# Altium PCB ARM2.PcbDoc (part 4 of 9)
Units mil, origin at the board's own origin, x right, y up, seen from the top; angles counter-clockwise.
Board outline 4700.79 x 3937.01 mil, 6 copper layers (Top Layer, GND02, ART03, ART04, PWR05, Bottom Layer); 697 components, 508 nets, 2326 pads, 1231 vias.
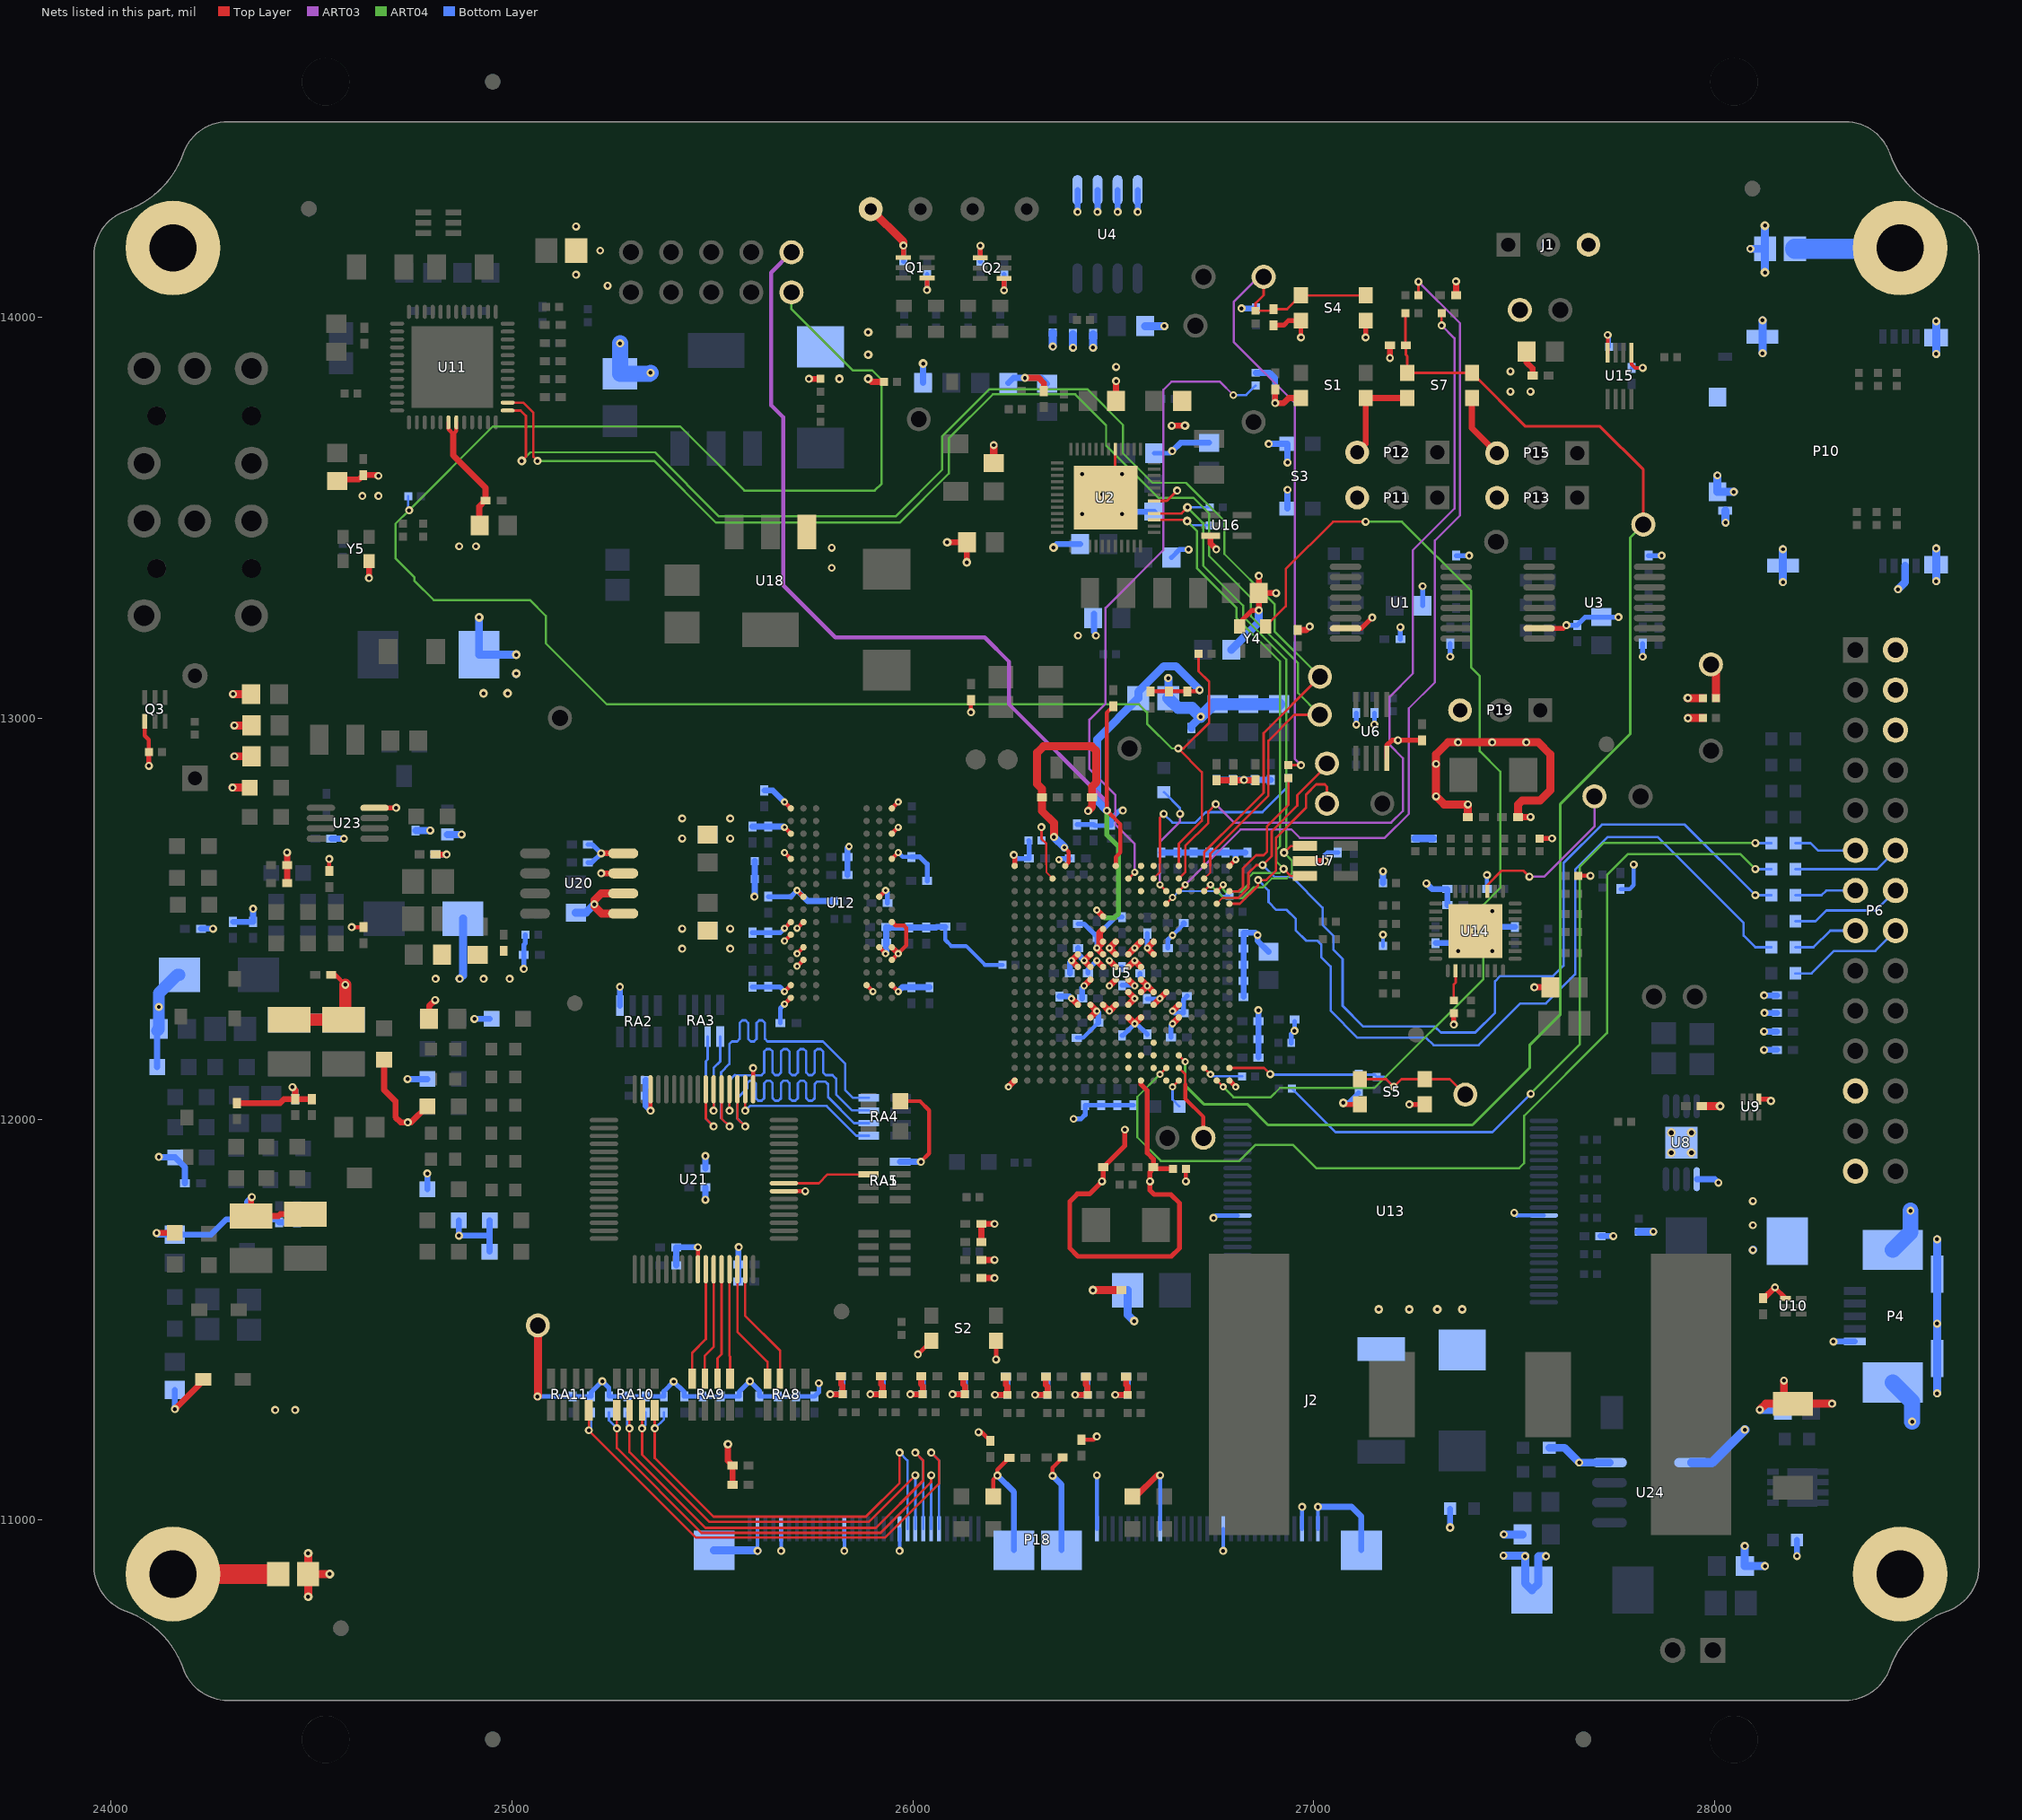
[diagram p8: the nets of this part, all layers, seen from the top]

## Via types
v1: diameter 20, hole 10, Top Layer to Bottom Layer, tented both sides, 871 vias
v2: diameter 18, hole 8, Top Layer to Bottom Layer, tented both sides, 273 vias
v3: diameter 22, hole 10, Top Layer to Bottom Layer, tented both sides, 64 vias
v4: diameter 20, hole 10, Top Layer to Bottom Layer, 18 vias
v5: diameter 22, hole 12, Top Layer to Bottom Layer, 4 vias
v6: diameter 39.37, hole 19.68, Top Layer to Bottom Layer, 1 vias

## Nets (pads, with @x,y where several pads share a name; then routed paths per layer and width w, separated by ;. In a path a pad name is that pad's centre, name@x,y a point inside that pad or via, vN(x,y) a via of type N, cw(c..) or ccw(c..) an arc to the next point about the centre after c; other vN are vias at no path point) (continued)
DGND: C1.1 C2.1 C3.1 C4.1 C5.2 C6.2 C7.1 C8.1 C9.1 C10.1 C11.1 C12.1 C13.1 C14.1 C15.1 C16.2 C17.2 C18.2 C19.2 C20.2 C23.2 C24.2 C27.2 C28.2 C29.2 C30.2 C34.2 C35.2 C36.2 C37.2 C38.2 C39.1 C40.1 C41.2 C42.2 C43.2 C44.2 C45.2 C46.2 C47.2 C48.2 C49.2 C50.2 C51.2 C52.2 C53.2 C54.2 C55.1 C56.1 C57.1 C58.2 C59.2 C60.1 C61.1 C62.1 C63.2 C64.2 C65.2 C66.2 C67.2 C68.1 C69.1 C70.1 C71.1 C72.1 C73.1 C74.1 C75.1 C76.1 C77.2 C78.2 C79.2 C80.2 C81.2 C82.2 C83.2 C84.2 C85.2 C86.2 C87.2 C88.2 C89.2 C90.2 C91.2 C92.2 C94.2 C95.1 C96.1 C97.2 C98.2 C99.2 C100.2 C101.2 C102.2 C103.2 C104.2 C105.2 C106.2 C107.2 C108.2 C109.2 C110.2 C111.2 C112.2 C113.2 C114.2 C115.2 C116.2 C117.2 C118.1 C119.2 C120.2 C121.2 C122.1 C123.2 C124.2 C125.2 C126.1 C127.2 C128.2 C129.2 C131.2 C132.2 C133.1 C134.2 C135.2 C136.2 C137.2 C138.2 C139.2 C140.2 C141.2 C142.2 C143.2 C145.2 C146.2 C147.2 C148.2 C149.2 C150.1 C151.2 C152.2 C153.2 C154.2 C155.1 C156.2 C157.2 C158.2 C159.2 C160.2 C161.2 C162.2 C163.2 C164.2 C165.2 C166.2 C167.2 C168.2 C169.2 C170.2 C171.2 C172.2 C173.2 C174.2 C189.2 C190.1 C191.2 C192.1 C197.2 C198.2 C199.2 C200.2 C201.2 C202.2 C204.1 C205.1 C206.1 C207.2 C208.2 C209.2 C210.2 C211.2 C212.2 C213.2 C214.2 C215.2 C216.2 C217.2 C218.2 C219.2 C220.2 C221.2 C222.2 C223.2 C224.2 C225.2 C226.2 C227.2 C228.2 C229.2 C230.2 C231.2 C232.2 C233.2 C234.2 C235.2 C236.2 C237.2 C238.2 C239.2 C240.2 C242.1 C243.1 C244.1 C245.1 C246.1 C249.1 C250.2 C251.1 C252.1 C253.1 C254.1 C256.2 C257.2 C258.1 C260.1 C261.1 C262.2 C263.2 C264.2 C265.2 C266.2 C267.2 C268.2 C269.2 C270.2 C271.2 C272.2 C273.2 C274.2 C275.2 C276.2 C277.2 C281.2 C282.2 D10.2 FB3.2 FB9.2 FB10.1 FB11.1 J1.3 J2.1 P4.5 P6.2 P6.4 P6.6 P6.23 P6.27 P10.6 P10.9 P11.3 P12.3 P13.3 P15.3 P18.2 P18.5 P18.13 P18.20 P18.31 P18.32 P18.33 P18.41 P18.49 P18.59 P18.61 P18.63 P18.64 P19.3 Q1.1 Q1.4 Q2.1 Q2.4 Q3.1 R10.2 R12.1 R22.1 R25.2 R34.2 R36.2 R39.1 R49.1 R53.2 R54.1 R76.2 R77.2 R78.2 R79.2 R80.2 R81.2 R82.2 R83.2 R84.2 R85.2 R86.2 R87.2 R88.2 R89.2 R90.2 R91.2 R92.2 R93.2 R94.2 R95.2 R96.1 R99.1 R100.2 R110.2 R115.2 R116.2 R117.2 R118.2 R130.1 R132.1 R135.2 R144.2 R145.2 R149.2 R164.2 R165.2 R169.2 R170.2 R173.1 R175.2 R176.1 R178.2 R190.2 R191.2 R198.2 R199.2 R201.1 R207.2 R208.2 R209.2 R210.2 R214.1 R215.1 R217.1 R238.2 RA2.1 RA5.1 S1.1 S1.3 S2.2 S2.4 S3.1 S3.3 S4.1 S4.3 S5.1 S5.3 S7.1 S7.3 TP1.1 TP8.1 TP9.1 U1.15 U2.30 U2.41 U2.49 U3.15 U4.5 U4.6 U4.7 U4.8 U5.A1 U5.A18 U5.F8 U5.G8 U5.G9 U5.G11 U5.G12 U5.H6 U5.H7 U5.H8 U5.H9 U5.H10 U5.H12 U5.J6 U5.J7 U5.J8 U5.J9 U5.J10 U5.J11 U5.K7 U5.K9 U5.K10 U5.K11 U5.L10 U5.L11 U5.L12 U5.L13 U5.M6 U5.M7 U5.M8 U5.M9 U5.M10 U5.M12 U5.M14 U5.N7 U5.N10 U5.N11 U5.N14 U5.V1 U5.V18 U6.4 U7.2 U8.1 U8.9 U9.4 U10.4 U11.42 U11.43 U12.A9 U12.B1 U12.B3 U12.B9 U12.D1 U12.D8 U12.E1 U12.E2 U12.E8 U12.F9 U12.G1 U12.G8 U12.G9 U12.J2 U12.J8 U12.M1 U12.M9 U12.P1 U12.P9 U12.T1 U12.T9 U13.13 U13.36 U14.33 U15.1 U15.4 U16.3 U18.1 U20.5 U20.6 U20.7 U20.8 U21.25 U21.39 U21.49 U21.62 U23.4 U24.4 U24.5 Y4.2 Y5.2 | length 23904.7
  Top Layer w7: v4(26472.19,13558.86) 26504.67,13591.34 U2.41@26504.67,13671.06 ; U2.30@26602.12,13542.13 26633.68,13542.13 v1(26659.45,13567.9)
  Top Layer w9: U15.4@27733.1,13911.57 v1(27733.12,13955.69) ; U15.1@27792.12,13911.57 27792.12,13882.76 27801.31,13873.57 v1(27820.31,13873.57)
  Top Layer w10: Q3.1@24084.6,12992.54 24084.6,12956.66 24095.05,12946.21 R34.2@24095.05,12915.07 ; C265.2@24545,12619 v1(24545,12648.91) ; C266.2@24550,12360 24560,12360 v1(24585,12335) ; v1(24601,12479) C264.2@24630,12479 ; U11.42@24842.16,13737.82 24842.16,13720.46 24854,13708.62 24861.84,13716.46 U11.43@24861.84,13737.82 ; v1(25346.1,12021.21) U21.62@25346.1,12074.41 ; U21.25@25464.21,11625.59 v1(25464.21,11680.79) ; U21.49@25602.01,12074.41 v1(25602.01,12127.61) ; U21.39@25678.78,11820.47 v1(25731.98,11820.48) ; v2(25680.27,12287.01) U12.A9@25696.02,12302.75 ; v2(25680.27,12318.51) U12.B9@25696.02,12334.25 ; v2(25680.27,12444.49) U12.F9@25696.02,12460.23 ; v2(25680.27,12475.99) U12.G9@25696.02,12491.73 ; v2(25680.27,12664.96) U12.M9@25696.02,12649.21 ; v2(25680.27,12727.95) U12.P9@25696.02,12712.2 ; v2(25680.27,12790.94) U12.T9@25696.02,12775.19 ; v2(25711.77,12381.5) U12.D8@25727.51,12397.24 ; v2(25711.77,12412.99) U12.E8@25727.51,12428.73 ; v2(25711.77,12475.99) U12.G8@25727.51,12491.73 ; v2(25711.77,12570.47) U12.J8@25727.51,12554.72 ; U12.B3@25884.99,12334.25 v2(25900.73,12318.51) ; U12.E2@25916.49,12428.73 v2(25932.23,12412.99) ; U12.J2@25916.49,12554.72 v2(25932.23,12570.47) ; U12.B1@25947.98,12334.25 v2(25963.73,12318.51) ; U12.D1@25947.98,12397.24 v2(25963.73,12412.99) ; U12.G1@25947.98,12491.73 25956.71,12483 25978,12483 25984,12477 25984,12433.27 v2(25963.73,12412.99) ; U12.M1@25947.98,12649.21 v2(25963.73,12664.96) ; U12.P1@25947.98,12712.2 v2(25963.73,12727.95) ; U12.T1@25947.98,12775.19 v2(25963.73,12790.94) ; R191.2@25968.74,12045 26018,12045 26041,12022 26041,11914.49 v1(26020.26,11893.74) ; v1(26145,13015) C106.2@26145,13045 ; v1(26164,11219.62) 26171.61,11219.62 C207.2@26193.28,11197.95 ; R169.2@26200.39,11059.16 26200.39,11101.01 v1(26211,11111.62) 26211,11125.62 C231.2@26241,11155.62 ; v1(26349,11110.62) 26349,11131.62 C211.2@26374,11156.62 ; C232.2@26421,11200.62 26451,11200.62 v1(26459,11208.62) ; v1@26681.27,11844.75 R110.2@26681.27,11875.57 ; U5.A18@26789.7,12631.72 v2(26805.45,12647.47) ; R144.2@27660,12607 v1(27690,12607)
  Top Layer w11: v1(26012.79,11413.62) S2.4@26046.29,11447.12 ; v1(26207.71,11400.91) S2.2@26207.71,11447.12
  Top Layer w12: v1(24095.05,12881.21) R34.2@24095.05,12915.07 ; U23.4@24657.93,12776.39 v1(24711.8,12776.39) ; Q1.4@25976.67,14148.81 v1(25976.67,14178.69) ; v1(26035.72,14067.75) Q1.1@26035.72,14097.63 ; Q2.4@26168.67,14148.18 v1(26168.67,14178.06) ; v1(26227.72,14067.12) Q2.1@26227.72,14097 ; v1(26252,12659.28) 26254.26,12657.02 U5.A1@26254.26,12631.72 ; U5.V18@26789.7,12096.28 v2(26805.45,12080.54) ; Y4.2@26815,13229 26815,13238.45 26845.55,13269 v1(26863,13269) ; C145.2@26900,13980 26925.46,13980 26936.96,13991.5 S4.1@26968.02,13991.5 v1(26968.02,13949.57) ; v3(27073.5,12040.88) 27077.5,12036.88 S5.1@27115.29,12036.88 ; U1.15@27079.41,13224.01 27118.92,13224.01 v1(27145.86,13250.94) ; v1(27129.44,13949.57) S4.3@27129.44,13991.5 ; U6.4@27182,12900 27182,12932 27195,12945 v1(27209.96,12945) C27.2@27270,12945 ; v1(27238.5,12036.88) S5.3@27276.71,12036.88 ; v1(27349.22,12236.06) R145.2@27349.22,12263.92 ; U3.15@27562.07,13224.01 27622.01,13224.01 v1(27630,13232) ; R135.2@27563.11,12700.14 v1(27594.55,12700.14) ; U9.4@28109.81,12050.26 28135.44,12050.26 v3(28140.12,12045.57) ; v1@28149.58,11580.03 U10.4@28176.31,11553.3
  Top Layer w15: v1(24114.37,11716.37) R217.1@24160,11716.37 ; v1(24160,11277) 24230.79,11347.79 D10.2@24230.79,11351.5 ; C276.2@24315,12040 24422,12040 24432,12050 C274.2@24460,12050 ; v1(24352,11806) 24350,11804 C246.1@24350,11758.31 24418,11758.31 24423,11763.31 C245.1@24485,11763.31 ; C267.2@24440,12589 C269.2@24440,12634 v1(24440,12665) ; v1(24453,12080) 24460,12073 C274.2@24460,12050 ; C258.1@24502,12050 C274.2@24460,12050 ; C192.1@24564.73,13591.35 24568.73,13595.35 24618.73,13595.35 C191.2@24629.73,13606.35 24665.47,13606.35 v1(24667.47,13604.35) ; v1(24644,13349.7) Y5.2@24644,13391.48 v1@24644,13350.7 ; R214.1@24681.81,12148.23 24681.81,12073.19 24710,12045 24710,12005 24723,11992 v1(24741,11992) 24749.13,11992 R198.2@24789.63,12032.5 ; C250.2@24794,12250 24794,12282 v1(24809,12297) ; C212.2@24805,12660 C212.2@24810,12660 v1(24837.37,12660) ; 24854,13708.62 24854,13655.62 24934.79,13574.83 24934.79,13544.63 24933.89,13543.73 24933.89,13542.83 24919.12,13528.06 C190.1@24919.12,13491.57 ; v1(25223,12613) U20.7@25278,12613 ; v1(25223,12663) U20.8@25278,12663 ; v3(25539.12,11189.57) 25539.12,11148.33 C216.2@25550.72,11136.73 C219.2@25550.72,11087.73 ; v1(25741.27,13846.27) R36.2@25770,13846.27 ; v1(25794.19,11313.94) R95.2@25825.05,11313.94 25825.05,11335.08 25821.19,11338.94 C173.2@25821.19,11358.94 ; v3(25889.12,13846.57) 25897.08,13838.62 R12.1@25928.86,13838.62 ; v1(25894.19,11313.94) R93.2@25925.05,11313.94 25925.05,11335.08 25921.19,11338.94 C172.2@25921.19,11358.94 ; U12.E1@25947.98,12428.73 v2(25963.73,12412.99) ; v1(25994.19,11313.94) R91.2@26025.05,11313.94 26025.05,11335.08 26021.19,11338.94 C169.2@26021.19,11358.94 ; v3(26086.08,13438.62) C1.1@26135,13438.62 v3(26135,13388.7) ; v1(26099.19,11313.94) R89.2@26130.05,11313.94 26130.05,11335.08 26126.19,11338.94 C162.2@26126.19,11358.94 ; C223.2@26171,11604 v1(26204,11604) ; C222.2@26171,11649 v1(26204,11649) ; C221.2@26171,11694 C220.2@26171,11739 v1(26204,11739) ; v1(26205.09,11312.56) R87.2@26235.94,11312.56 26235.94,11333.7 26232.09,11337.56 C160.2@26232.09,11357.56 ; v2(26238.51,12080.54) U5.V1@26254.26,12096.28 ; v1(26279.72,13848.72) 26314.28,13848.72 26327,13836 C3.1@26327,13816 ; v1(26305.09,11312.56) R83.2@26335.94,11312.56 26335.94,11333.7 26332.09,11337.56 C167.2@26332.09,11357.56 ; v1(26405.09,11312.56) R82.2@26435.94,11312.56 26435.94,11333.7 26432.09,11337.56 C166.2@26432.09,11357.56 ; v1(26505.09,11312.56) R81.2@26535.94,11312.56 26535.94,11333.7 26532.09,11337.56 C165.2@26532.09,11357.56 ; C15.1@26507,13791 v1(26507,13841) ; R170.2@26548.08,11059.16 26556.34,11059.16 26609.22,11112.04 v1(26616.77,11112.04) ; v2(26584.97,12426.99) U5.H12@26600.72,12411.24 ; v1(26646.12,13729.57) v3(26679.12,13729.57) ; U16.3@26742.63,13455.41 26742.63,13435.37 v1(26757,13421) ; C53.2@26758.02,12845 C48.2@26800,12845 v1@26825,12845 ; v1(26826,12846) v1@26825,12845 ; C54.2@26855,12845 v1@26825,12845 ; v1(26863,13269) C12.1@26863,13312 ; v1(26863,13355) C12.1@26863,13312 ; C24.2@26903.73,13820 v1(26903.73,13785.86) 26925,13785.86 26937.64,13798.5 S1.1@26968.02,13798.5 ; v1(26906,13312) C12.1@26863,13312 ; C159.2@26960,13220 26981.55,13220 v1(26990.12,13228.57) ; U7.2@26978,12644 v1(27028,12644) ; P12.3@27108.26,13663 27129.44,13684.18 S1.3@27129.44,13798.5 S7.1@27233.02,13798.5 ; C148.2@27190,13930 27190,13898.7 v1(27190.12,13898.57) ; C30.2@27355,14055 v1(27355,14089.45) ; S7.3@27394.44,13798.5 27394.44,13723.56 P15.3@27457,13661 ; C142.2@27509.3,12753.4 v1(27540.74,12753.4) ; C153.2@27531,13914.15 27531,13887.15 27546,13872.15 C154.2@27546,13854.15 ; v1(27550,12329) C133.1@27590,12329 ; C36.2@28123.17,11553.62 v1@28149.58,11580.03 ; R176.1@28172.62,11312.99 R176.1@28195.13,11290.49
  Top Layer w16: v2(26395.99,12301.01) U5.M6@26411.74,12285.26 ; U5.J6@26411.74,12379.75 v2(26395.99,12395.5) U5.H6@26411.74,12411.24 ; v2(26427.49,12332.51) U5.K7@26443.24,12348.25 ; U5.N7@26443.24,12253.76 v2(26458.99,12269.52) U5.M7@26443.24,12285.26 ; U5.J7@26443.24,12379.75 v2(26427.49,12395.5) U5.H7@26443.24,12411.24 ; v2(26458.99,12395.5) U5.J8@26474.74,12379.75 ; U5.M8@26474.74,12285.26 v2(26490.48,12269.52) U5.M9@26506.23,12285.26 ; U5.H8@26474.74,12411.24 v2(26458.99,12426.99) U5.G8@26469.18,12437.19 ; U5.G8@26474.74,12442.74 U5.G8@26469.18,12437.19 ; U5.F8@26474.74,12474.24 26466.1,12465.6 26466.1,12448.59 ; v2(26490.48,12332.51) U5.K9@26506.23,12348.25 ; v2(26490.48,12395.5) U5.J9@26506.23,12379.75 ; U5.H9@26506.23,12411.24 v2(26490.48,12426.99) U5.G9@26506.23,12442.74 ; U5.N10@26537.73,12253.76 v2(26553.48,12238.02) U5.N11@26569.22,12253.76 ; U5.M10@26537.73,12285.26 v2(26553.48,12301.02) U5.L10@26537.73,12316.76 ; U5.K10@26537.73,12348.25 v2(26553.48,12332.51) ; U5.J10@26537.73,12379.75 v2(26553.48,12395.5) U5.J11@26569.22,12379.75 ; U5.H10@26537.73,12411.24 v2(26553.48,12426.99) ; v2(26553.48,12426.99) U5.G11@26569.22,12442.74 ; U5.L11@26569.22,12316.76 v2(26584.97,12332.51) ; U5.K11@26569.22,12348.25 v2(26584.97,12332.51) ; v2(26584.97,12426.99) U5.G12@26600.72,12442.74 ; U5.M12@26600.72,12285.26 v2(26616.47,12301.02) U5.L13@26632.22,12316.76 ; U5.L12@26600.72,12316.76 v2(26584.97,12332.51) ; v2(26647.96,12238.02) U5.N14@26663.71,12253.76 ; v2(26647.96,12269.52) U5.M14@26663.71,12285.26 ; 26466.1,12448.59 26469.18,12445.51 U5.G8@26469.18,12437.19 ; 26466.1,12448.59 26466.1,12440.27 U5.G8@26469.18,12437.19
  Top Layer w20: v1(24304,12827) R215.1@24346.63,12827 ; v1(24305,13060) C243.1@24350,13060 ; v1(24308.37,12905) C244.1@24351,12905 ; v1(24308.37,12982) C242.1@24351,12982 ; v3(24492.53,10808.97) FB10.1@24492.53,10865.57 ; v3(24492.53,10917.57) FB10.1@24492.53,10865.57 ; v3(24546.12,10865.57) FB10.1@24492.53,10865.57 ; v1(25064,11308.62) 25065.12,11309.75 TP1.1@25065.12,11485.57 ; U20.5@25278,12513 25224,12513 25206,12531 v1(25206,12536) 25206,12546 25223,12563 U20.6@25278,12563 ; TP8.1@25895.12,14269.57 25976.67,14188.03 v1(25976.67,14178.69) ; C2.1@26202,13636 v1(26202,13681) ; v3(26449.12,11573.57) 26449.17,11573.62 C125.2@26520,11573.62 ; C143.2@27384.3,12753.4 v1(27384.3,12784.84) 27325.16,12784.84 v1(27305,12805) v1(27305,12886) 27305,12910 27335,12940 v1(27360,12940) v1(27445,12940) v1(27530,12940) 27560,12940 27590,12910 27590,12820 27565,12795 27520,12795 27510,12785 C142.2@27510,12754.1 ; v3(27932.77,13050.5) 27933.01,13050.26 R132.1@27970.75,13050.26 ; v3@27933.1,13000.14 v3(27933.22,13000.26) R130.1@27970.75,13000.26 ; C35.2@27967.7,12032.36 v3(28013.34,12032.36) ; v1(28112.62,11275.57) 28127.55,11290.49 R176.1@28195.13,11290.49 v1(28292.55,11290.49) ; R176.1@28172.62,11312.99 v1(28172.62,11348.07)
  Top Layer w30: C251.1@24445,12247.99 C252.1@24580,12247.99 24585,12252.99 v1(24585,12335)
  ART04 w20: v5@27942.1,11966.54 v5@27942.68,11965.95
  Bottom Layer w9: v1(25612.83,10923.24) P18.2@25612.83,10978.27 ; v1(25671.89,10923.24) P18.5@25671.89,10978.27 ; v1(25829.37,10923.24) P18.13@25829.37,10978.27 ; v1(25967.17,10923.24) P18.20@25967.17,10978.27 ; v1(26774.25,10923.24) P18.49@26774.25,10978.27 ; v1(27733.12,13955.69) 27736.68,13952.13 R165.2@27736.68,13926.57 ; C155.1@27792.62,13873.57 v1(27820.31,13873.57)
  Bottom Layer w10: v2(25963.73,12664.96) 25974.69,12654 C110.2@25997,12654 ; C28.2@26081,12480 26081,12447 26096,12432 26133,12432 26180,12385 R22.1@26223.86,12385 ; C38.2@26409,12203 26425,12203 C56.1@26463,12241 ; P18.33@26459.29,10978.27 v1(26459.29,11112.04) ; P18.41@26616.77,10978.27 v1(26616.77,11112.04) ; v2(26647.96,12458.5) C65.2@26675.96,12486.5 ; P18.59@26971.1,10978.27 v1(26971.1,11033.3) ; P18.61@27010.47,10978.27 v1(27010.47,11033.3) ; R115.2@27172.72,12432 v1(27172.72,12460.12) ; C131.2@27432.06,12574 v1(27432.06,12609) ; v1@27506.62,11760 U13.13@27573.78,11760 ; C141.2@27765,12574 27788,12574 27798,12584 v1(27798,12635)
  Bottom Layer w11: v1(26750,11753.62) 26755.94,11759.57 26755.94,11760 U13.36@26810,11760 ; v1(27500,11766.62) v1@27506.62,11760
  Bottom Layer w12: v1(25030,12375) C201.2@25030,12410 25030,12435 25033.86,12438.86 R149.2@25033.86,12460 ; v1(25064,11308.62) C240.2@25152.2,11308.62 C239.2@25197.97,11308.62 25197.97,11318.59 v1(25226,11346.62) 25242.24,11330.39 C238.2@25242.24,11308.62 C237.2@25288,11308.62 C236.2@25333.76,11308.62 C235.2@25379.53,11308.62 25379.53,11321.15 v1(25404,11345.62) 25429.95,11319.67 C234.2@25429.95,11308.62 C233.2@25475.71,11308.62 C229.2@25521.48,11308.62 C228.2@25567.24,11308.62 25567.24,11319.87 v1(25594,11346.62) 25617.71,11322.92 C227.2@25617.71,11308.62 C226.2@25663.47,11308.62 C225.2@25709.24,11308.62 C224.2@25755,11308.62 25766,11319.62 v1(25766,11341.62) ; C87.2@25190,12640 25200,12640 v1(25223,12663) 25201,12685 C69.1@25190,12685 ; C98.2@25600,12330 C120.2@25640,12330 25668.78,12330 v2(25680.27,12318.51) ; C102.2@25600,12465 C116.2@25640,12465 25669.29,12465 v2(25680.27,12475.99) ; C108.2@25640,12555 25696.3,12555 v2(25711.77,12570.47) ; C107.2@25670,12240 25670,12276.73 v2(25680.27,12287.01) ; v2(25932.23,12570.47) 25937,12565.7 C117.2@25937,12539 ; R77.2@25976.67,14139.36 v1(25976.67,14178.69) ; C110.2@25997,12654 26018,12654 26036,12636 C112.2@26036,12594 ; v1(26035.72,14067.75) R76.2@26035.72,14107.07 ; R79.2@26168.67,14138.73 v1(26168.67,14178.06) ; v1(26227.72,14067.12) R78.2@26227.72,14106.44 ; v1(26252,12659.28) 26261.28,12650 C81.2@26290,12650 26290,12693.86 R54.1@26288.86,12695 ; v2(26364.5,12647.47) 26367.04,12650 C105.2@26391.74,12650 ; v1(26401.17,12000.75) 26419.75,12000.75 26430,12011 C71.1@26430,12035 C68.1@26470,12035 C57.1@26510,12035 C67.2@26550,12035 ; C104.2@26410,12735 C89.2@26450.54,12735 26453.54,12732 26494.72,12732 R164.2@26495,12732.28 26495,12749.19 26515.81,12770 v1(26523.85,12770) ; C100.2@26412,12487 26427.47,12487 C94.2@26458.99,12455.48 ; C43.2@26436.98,12364 26436.98,12373.48 v2(26458.99,12395.5) ; v2(26458.99,12426.99) C94.2@26458.99,12454.28 C94.2@26458.99,12455.48 ; v2(26490.48,12395.5) 26506.98,12379 C47.2@26521.98,12379 ; C52.2@26521.98,12209 26524.46,12209 v2(26553.48,12238.02) 26558.48,12238.02 C79.2@26584.97,12211.53 ; C50.2@26521.98,12334 26551.98,12334 v2(26553.48,12332.51) ; C64.2@26521.98,12504 26505.78,12504 26458.99,12457.21 C94.2@26458.99,12455.48 ; C49.2@26566.98,12364 26566.98,12350.49 v2(26584.97,12332.51) ; C51.2@26584,12300 26615.45,12300 v2(26616.47,12301.02) ; v2(26584.97,12426.99) C70.1@26584.97,12462.98 ; C13.1@26602,13661 26642,13661 v1(26647,13666) ; C92.2@26635.96,12426.99 26635.96,12446.5 v2(26647.96,12458.5) ; C78.2@26643.98,12204 26643.98,12234.03 v2(26647.96,12238.02) ; C7.1@26645.12,13400.57 26665.12,13420.57 v1(26688.12,13420.57) ; v2(26647.96,12269.52) 26652.96,12264.52 C86.2@26675.45,12264.52 26675.45,12298.45 C85.2@26684,12307 ; R49.1@26943.85,12190.18 26943.85,12212.25 v1(26952,12220.4) ; v1@26952.38,12221.38 C88.2@26952.38,12244 ; v1(27028,12644) 27028,12658.55 27034.45,12665 C152.2@27060,12665 ; v3(27073.5,12040.88) 27087,12040.88 C146.2@27112,12065.88 ; v1(27106.2,12984) C72.1@27106.2,13013 ; v1(27151.4,12984) C73.1@27151.4,13013 ; C127.2@27216,13197 v1(27216,13227) ; C126.1@27271.62,13280.57 v1(27271.62,13329.08) ; v1(27340.2,13153.4) C128.2@27340.2,13186 ; C129.2@27355,13405.4 v1(27387.6,13405.4) ; v1(27630,13232) C151.2@27657,13232 27677,13252 C150.1@27717,13252 v1(27760,13252) ; v1(27820.2,13153.4) C158.2@27820.2,13186 ; C174.2@27835,13405.4 v1(27867.6,13405.4)
  Bottom Layer w15: v1(24114.37,11716.37) 24118.74,11712 C261.1@24160,11712 24250,11712 24288.43,11750.43 R201.1@24340,11750.43 ; R178.2@24115.63,12130 C206.1@24115.63,12220.63 ; v1(24120,11906) 24121,11905 R238.2@24160.63,11905 24185,11880.63 C277.2@24185,11840 ; v1(24160,11277) C260.1@24160,11325 ; C271.2@24225,12475 v1(24255,12475) ; C270.2@24305,12492 C268.2@24355,12492 v1(24355,12525) ; v1(24352,11806) 24340,11794 R201.1@24340,11750.43 ; v1(24453,12080) 24460,12073 C272.2@24460,12050 ; C273.2@24465,11743 C275.2@24420,11743 24412.57,11750.43 R201.1@24340,11750.43 ; C249.1@24550.2,12699.61 v1(24581.61,12699.61) ; C253.1@24580,12247.99 24580,12330 v1(24585,12335) ; v1(24740,12100) R199.2@24789.63,12100 ; R210.2@24789.63,11825 v1(24789.63,11864.37) ; C215.2@24810,12660 v1(24837.37,12660) ; R190.2@24868.37,11748 v1(24868.37,11709.63) 24868.74,11710 24944.63,11710 ; v1(24907,12250) R207.2@24944.63,12250 ; R208.2@24944.63,11670 24944.63,11710 ; R209.2@24945,11748 24944.63,11747.63 24944.63,11710 ; RA2.1@25269.76,12283.37 v1(25269.76,12330.24) ; C209.2@25334,12098 C210.2@25334,12058 25334,12033.31 v1(25346.1,12021.21) ; C218.2@25410.12,11635.57 C230.2@25410.12,11680.57 25463.99,11680.57 v1(25464.21,11680.79) ; v1(25483,11799) C214.2@25483,11830 ; C217.2@25483,11877 v1(25483,11908) ; C213.2@25565,11595 25565,11637.63 C208.2@25565.37,11638 25565.37,11680.37 v1(25566,11681) ; C97.2@25600,12730 C113.2@25640,12730 ; v1(25605,12555) 25605.86,12555.86 R96.1@25605.86,12598.97 R99.1@25605.86,12643.97 ; C113.2@25630,12730 C113.2@25640,12730 ; C119.2@25630,12820 25651.21,12820 v2(25680.27,12790.94) ; v2(25680.27,12727.95) 25678.22,12730 C113.2@25640,12730 ; v2(25711.77,12570.47) 25738.26,12543.97 R100.2@25804.72,12543.97 ; v1(25794.19,11313.94) R94.2@25825.05,11313.94 25825.05,11355.08 C171.2@25821.19,11358.94 ; v3@25816.82,13846.27 v3(25817.12,13846.57) ; C124.2@25837,12608.97 C123.2@25837,12653.97 25837,12676 v2(25841,12680) ; v1(25894.19,11313.94) R92.2@25925.05,11313.94 25925.05,11355.08 C170.2@25921.19,11358.94 ; v2(25932.23,12412.99) 25934,12414.75 C101.2@25934,12440 C114.2@25934,12479 25935,12478 C121.2@25991.08,12478 C111.2@26034,12478 26058,12478 26060,12480 C28.2@26081,12480 ; v2(25963.73,12318.51) 25974.22,12329 C109.2@25997,12329 C115.2@26042,12329 ; RA5.1@25968.37,11893.74 v1(26020.26,11893.74) ; v1(25994.19,11313.94) R90.2@26025.05,11313.94 26025.05,11355.08 C163.2@26021.19,11358.94 ; C18.2@26025.86,13836.62 v3(26025.86,13884.57) ; v1(26099.19,11313.94) R88.2@26130.05,11313.94 26130.05,11355.08 C161.2@26126.19,11358.94 ; v1(26205.09,11312.56) R86.2@26235.94,11312.56 26235.94,11353.7 C157.2@26232.09,11357.56 ; v1(26211,11111.62) 26252.6,11070.02 P18.32@26252.6,10925.12 ; C16.2@26238.4,13836 26251.12,13848.72 v1(26279.72,13848.72) 26320.28,13848.72 C4.1@26335,13834 ; v1(26305.09,11312.56) R85.2@26335.94,11312.56 26335.94,11353.7 C156.2@26332.09,11357.56 ; v1(26349,11110.62) 26370.71,11088.91 P18.64@26370.71,10925.12 ; v3(26351,13425.63) 26359.31,13433.94 C8.1@26417.44,13433.94 ; C58.2@26366,12306 26391,12306 v2(26395.99,12301.01) ; C103.2@26391.98,12364 26391.98,12391.48 v2(26395.99,12395.5) ; v1(26405.09,11312.56) R84.2@26435.94,11312.56 26435.94,11353.7 C168.2@26432.09,11357.56 ; v1(26410.92,14262.88) U4.5@26410.92,14316.88 ; C99.2@26412.49,12426.99 26412.49,12410.5 v2(26427.49,12395.5) ; C44.2@26422.48,12301.02 26422.48,12327.5 v2(26427.49,12332.51) ; 26452,13215 C9.1@26452,13261 ; v2(26458.99,12269.52) 26463,12265.51 C56.1@26463,12241 ; v1(26460.92,14262.88) U4.6@26460.92,14316.88 ; v1(26505.09,11312.56) R80.2@26535.94,11312.56 26535.94,11353.7 C164.2@26532.09,11357.56 ; v1(26510.92,14262.88) U4.7@26510.92,14316.88 ; v4(26522.19,13508.86) 26528.33,13515 C10.1@26602,13515 ; v1(26560.92,14262.88) U4.8@26560.92,14316.88 ; C82.2@26620,12665 C91.2@26660,12665 C60.1@26700,12665 C59.2@26740,12665 C75.1@26780,12665 26805,12665 ; v1(26647,13666) 26668,13687 C11.1@26739,13687 ; C65.2@26675.96,12486.5 C65.2@26675.96,12489 ; C45.2@26758.02,12846 C46.2@26798.02,12846 v1(26826,12846) C41.2@26853.02,12846 C42.2@26893.02,12846 ; v2(26805.45,12647.47) 26805,12647.91 26805,12665 ; v1(26820,14022.2) 26820.2,14022 C29.2@26856.27,14022 ; C63.2@26825,12305 C66.2@26825,12345 C37.2@26825,12385 C74.1@26825,12425 C76.1@26825,12465 26854,12465 v1(26860,12459) 26860,12444.84 C77.2@26887.42,12417.42 ; C61.1@26830,12665 26805,12665 ; R25.2@26855.73,13861.14 26890.29,13861.14 26903.73,13847.7 v1(26903.73,13785.86) ; C83.2@26862,12154 C84.2@26862,12199 C80.2@26862,12244 v1(26862,12272) ; v1(26887.78,13684.33) S3.3@26934.5,13684.33 v1(26934.5,13637.61) ; S3.1@26934.5,13522.91 v1(26934.5,13569.63) ; v1(27010.47,11033.3) 27094.4,11033.3 27118.74,11008.96 P18.63@27118.74,10925.12 ; R117.2@27172.72,12589 v1(27172.72,12618.18) ; v1(27281,12588) 27295,12574 C134.2@27333.11,12574 C136.2@27333.11,12534 ; C135.2@27304.11,12439.15 27339.85,12439.15 v4(27360,12419) ; R175.2@27340,11028.62 27340,10990.45 27340,10981.7 v3(27340.12,10981.57) ; v3@27370,11525.62 v3(27370.12,11525.75) ; v4(27403.11,12469) 27413.56,12479.45 C132.2@27502.11,12479.45 ; C6.2@27715,11708.62 v1(27746.86,11708.62) ; U8.1@27955.2,11850.37 28000.33,11850.37 v1(28009.12,11841.57) ; v1(28122.9,12172.8) C138.2@28155,12172.8 ; v1(28122.9,12218.62) C137.2@28155,12218.62 ; v1(28122.9,12308.62) C139.2@28155,12308.62 ; v1(28123.9,12265) C140.2@28155,12265 C140.2@28156,12265 ; v1(28205.05,10910.65) R173.1@28205.05,10950.57 ; v1(28295.74,11445.63) P4.5@28349.64,11445.63
  Bottom Layer w18: C256.2@24761.63,12720 v1(24796.91,12720) ; C257.2@24840,12710.08 v1(24875.28,12710.08)
  Bottom Layer w20: v1(24870,12350) 24878.43,12358.43 C263.2@24878.43,12500 ; v3@24918.43,13251.3 C5.2@24918.43,13158.59 v3@25011.14,13158.59 ; v3@25010.69,13110.71 v3(25011.44,13111.46) ; C200.2@25160,12515 25185,12515 v1(25206,12536) ; P18.31@25504.57,10925.12 25610.95,10925.12 v1(25612.83,10923.24) ; v1(26349.54,13926.99) R10.2@26349.54,13961.73 ; v1(26399.54,13924.16) C19.2@26399.54,13957.88 ; v3(26449.12,11573.57) 26449.17,11573.62 C23.2@26535.94,11573.62 26535.94,11512.75 v3(26552.12,11496.57) ; v1(26449.54,13924.16) C20.2@26449.54,13957.88 ; C17.2@26579.54,13977.88 v1(26627.43,13977.88) ; FB3.2@26637.4,13050 v1@26637.4,13100 ; C90.2@26695.12,12975.91 C90.2@26695.12,12975.57 26695.12,12980.57 v1(26718.12,13003.57) ; C62.1@26794.06,13170.61 26863,13239.55 v1(26863,13269) ; R116.2@27253.11,12700.14 R118.2@27297.4,12700.14 ; v1(27473.12,10911.57) 27527.12,10911.57 v1(27527.12,10910.22) 27527.12,10842.59 C147.2@27544.14,10825.57 27560,10841.43 27560,10909 27561.22,10910.22 v1(27579.12,10910.22) ; v1(27474.12,10964.57) 27474.3,10964.4 C281.2@27520.97,10964.4 ; R39.1@27587.25,11180.49 27625.25,11180.49 v1(27662.12,11143.62) U24.4@27737.64,11143.62 ; R53.2@27810.12,11719.43 v1(27846.98,11719.43) ; P10.9@28026.37,13517.27 28026.37,13488.33 v1(28027.12,13487.57) ; v1(28075.12,10935.57) C199.2@28075.12,10885.57 v1(28125.12,10885.57) ; v1(28089.12,14170.57) FB11.1@28125.12,14170.57 ; v1(28095.12,11673.57) v1@28096.12,11674.57 ; v1(28112.62,11275.57) C282.2@28170.12,11275.57 ; v3(28125.12,14111.57) FB11.1@28125.12,14170.57 ; v3(28125.12,14228.57) FB11.1@28125.12,14170.57 ; v1(28457.12,13321.57) 28474.76,13339.21 P10.6@28474.76,13380.17
  Bottom Layer w23: U24.5@27942.36,11143.62 27993.17,11143.62 v1(28075.12,11225.57)
  Bottom Layer w30: C206.1@24115.63,12220.63 C206.1@24120,12225 v1(24120,12280) 24120,12314 24166,12360 C262.2@24171.57,12360 ; C254.1@24445,12247.99 C253.1@24580,12247.99 ; FB3.2@26637.4,13050 26661.83,13025.57 26696.12,13025.57 v1(26718.12,13003.57) 26749.55,13035 C40.1@26760,13035 ; C40.1@26754.22,13035 C40.1@26760,13035 ; C39.1@26914,13035 C55.1@26837,13035 C40.1@26760,13035
  Bottom Layer w40: v1(25270,13935) C197.2@25270,13859.06 25343.61,13859.06 v1(25346.12,13861.57)
  other v1: 24410,11275 24460,11275 28150.12,11580.57 28095.12,11735.57 28095.12,11795.57 26681.29,11844.73 24810,12350 24930,12350 24995,12350 25425,12425 25545,12425 25425,12475 25545,12475 25425,12700 25545,12700 25425,12750 25545,12750 26637,13100 26412,13206 26457,13206 25798,13375 25798,13425 24869,13428.62 24911,13428.62 24627.47,13554.35 24667.47,13554.35 27490.53,13814.62 27540.53,13814.62 27490.53,13864.62 26507,13876 25239,14078.62 25160.62,14106.07 25220.62,14166.07 25160.62,14226.07
  other v3: 27162.12,11525.75 27238.12,11525.75 27308.12,11525.75 24929.68,13061.9 24989.58,13061.9 25011.44,13158.28 24918.73,13251.6 25889.12,13906.57 25889.12,13962.57
  other v4: 27445,12419 27445,12519 26422.19,13508.86 26422.19,13608.86 26522.19,13608.86
  other v5: 27891.8,11916.37 27941.8,11916.37 27891.8,11966.37 27941.8,11966.37
EHRPWM1A: TP18.1 U5.U14 | length 199.5
  Top Layer w6: U5.U14@26663.71,12127.78 26679.91,12111.58 26679.91,12087
  Top Layer w10: 26679.91,12087 26679.91,12050.71 26725,12005.62 TP18.1@26725,11953.62
EHRPWM1B: C148.1 R40.2 S7.2 S7.4 TP19.1 U5.T14 | length 3494.1
  Top Layer w6: U5.T14@26663.71,12159.28 v2(26679.46,12143.54) ; R40.2@27228.86,14010 R40.2@27230,14008.86 ; S7.4@27394.44,13861.5 S7.4@27396.94,13859
  Top Layer w7: R40.2@27228.86,14010 27228.86,13931.14 C148.1@27230,13930 27230,13906.02 27233.02,13903 S7.2@27233.02,13861.5 S7.4@27394.44,13861.5 27528.09,13727.85 27713.78,13727.85 27822,13619.63 TP19.1@27822,13483
  ART04 w7: v2(26679.46,12143.54) 26679.46,12083.77 26725.88,12037.35 26834.27,12037.35 26886,11985.62 27395.75,11985.62 27539,12128.88 27539,12185.62 27615,12261.62 27615,12786.2 27789.4,12960.6 27789.4,13450.4 TP19.1@27822,13483
EHRPWM2A: U5.U10
EHRPWM2B: U5.T10
ENZ_KALDO_1P8V: R54.2 U5.B4 | length 173
  Top Layer w4.4: 26333,12636 26333,12615.97 U5.B4@26348.75,12600.22
  Top Layer w6: v1(26321,12728.32) 26321,12699 26333,12687 26333,12636
  Bottom Layer w6: v1(26321,12728.32) 26321.14,12728.17 R54.2@26321.14,12695
ETH_TXD4: R145.1 U14.18 | length 75.7
  Top Layer w6: R145.1@27349.22,12296.2 27349.22,12335.85 27353.86,12340.48 U14.18@27353.86,12370
FA_ARM_0: P6.12 R260.1 | length 269.1
  Bottom Layer w6: R260.1@28201.18,12623.62 28404.29,12623.62 P6.12@28450.94,12670.28
FA_ARM_1: P6.11 R253.2 | length 157.3
  Bottom Layer w6: R253.2@28201.26,12688.62 28239,12688.62 28257.35,12670.28 P6.11@28350.94,12670.28
FA_ARM_2: P6.14 R252.2 | length 281.5
  Bottom Layer w6: R252.2@28201.18,12493.62 28251.26,12493.62 28278.26,12520.62 28401.29,12520.62 P6.14@28450.94,12570.28
FA_ARM_3: P6.13 R251.2 | length 154.6
  Bottom Layer w6: R251.2@28201.18,12558.62 28266.26,12558.62 28277.91,12570.28 P6.13@28350.94,12570.28
FA_ARM_4: P6.16 R256.2 | length 293.9
  Bottom Layer w6: R256.2@28201.18,12363.62 28241.26,12363.62 28297.26,12419.62 28400.29,12419.62 P6.16@28450.94,12470.28
FA_ARM_5: P6.15 R255.2 | length 167
  Bottom Layer w6: R255.2@28201.18,12428.62 28246.26,12428.62 28287.91,12470.28 P6.15@28350.94,12470.28
GI_H0: RA3.6 U21.55 | length 335.1
  Top Layer w6: U21.55@25483.9,12074.41 25483.9,12001.52 v1(25503.58,11981.84)
  Bottom Layer w6: RA3.6@25488.5,12206.26 25488.5,12149 25484,12144.5 25484,12001.42 v1(25503.58,11981.84)
GI_H1: RA3.5 U21.54 | length 245.1
  Top Layer w6: v1(25503.58,12021.21) U21.54@25503.58,12074.41
  Bottom Layer w6: v1(25503.58,12021.21) 25503.58,12127.58 25520,12144 RA3.5@25520,12206.26
GI_H2: RA4.8 U21.53 | length 951.6
  Top Layer w6: U21.53@25523.27,12074.41 25523.27,12001.52 v1(25542.95,11981.84)
  Bottom Layer w6: v1(25542.95,11981.84) 25522,12002.79 25522,12117 25542.5,12137.5 25542.5,12187.5 25549,12194 25562.2,12194 25568.5,12200.3 25568.5,12240.14 25574.8,12246.44 25583.2,12246.44 25589.5,12240.14 25589.5,12200.3 25595.8,12194 25604.2,12194 25610.5,12200.3 25610.5,12240.14 25616.8,12246.44 25625.2,12246.44 25631.5,12240.14 25631.5,12200.3 25637.8,12194 25776,12194 25831.5,12138.5 25831.5,12072.5 25850.76,12053.24 RA4.8@25890.63,12053.24
GI_H3: RA4.7 U21.52 | length 1002.7
  Top Layer w6: v1(25542.95,12021.21) U21.52@25542.95,12074.41
  Bottom Layer w6: v1(25542.95,12021.21) 25542.95,12096.95 25556,12110 25556.39,12109.61 25622.81,12109.61 25629.5,12116.3 25629.5,12168.7 25635.8,12175 25644.2,12175 25650.5,12168.7 25650.5,12116.3 25656.8,12110 25665.2,12110 25671.5,12116.3 25671.5,12168.7 25677.8,12175 25686.2,12175 25692.5,12168.7 25692.5,12116.3 25698.8,12110 25707.2,12110 25713.5,12116.3 25713.5,12168.7 25719.8,12175 25728.2,12175 25734.5,12168.7 25734.5,12116.3 25740.8,12110 25749.2,12110 25755.5,12116.3 25755.5,12168.7 25761.8,12175 25770.2,12175 25776.5,12168.7 25776.5,12116.3 25782.8,12110 25800,12110 25809,12101 25809,12062 25849.25,12021.75 RA4.7@25890.63,12021.75
GI_H4: RA4.6 U21.51 | length 933
  Top Layer w6: U21.51@25562.64,12074.41 25562.64,12001.52 v1(25582.32,11981.84)
  Bottom Layer w6: v1(25582.32,11981.84) 25563,12001.16 25563,12052.8 25587.5,12077.3 25587.5,12089.7 25593.8,12096 25602.2,12096 25608.5,12089.7 25608.5,12052.3 25614.8,12046 25623.2,12046 25629.5,12052.3 25629.5,12089.7 25635.8,12096 25644.2,12096 25650.5,12089.7 25650.5,12052.3 25656.8,12046 25665.2,12046 25671.5,12052.3 25671.5,12089.7 25677.8,12096 25686.2,12096 25692.5,12089.7 25692.5,12052.3 25698.8,12046 25707.2,12046 25713.5,12052.3 25713.5,12089.7 25719.8,12096 25728.2,12096 25734.5,12089.7 25734.5,12052.3 25740.8,12046 25749.2,12046 25755.5,12052.3 25755.5,12087.5 25762,12094 25782,12094 25789,12087 25789,12055 25853.75,11990.25 RA4.6@25890.63,11990.25
GI_H5: RA4.5 U21.50 | length 397.1
  Top Layer w6: v1(25582.32,12021.21) U21.50@25582.32,12074.41
  Bottom Layer w6: v1(25582.32,12021.21) 25594.11,12033 25785,12033 25859.24,11958.76 RA4.5@25890.63,11958.76
GND_EARTH: FB10.2 FB11.2 MTG1.1 MTG2.1 MTG3.1 MTG4.1 P4.6 P4.7 P4.8 P4.9 P10.11 P10.12 P10.13 P10.14 P10.15 P10.16 | length 1553.1
  Top Layer w50: MTG3.1@24155.12,10865.57 FB10.2@24417.72,10865.57
  Bottom Layer w20: v1(28006.74,13605.47) P10.16@28006.74,13564.52 v1(28047.68,13564.52) ; v1(28119.06,13910.38) P10.11@28119.06,13951.32 v1(28119.06,13992.27) ; v1(28170.24,13339.52) P10.12@28170.24,13380.46 v1(28170.24,13421.41) ; v1(28552.12,13341.63) P10.14@28552.12,13382.57 v1(28552.12,13423.52) ; v1(28552.12,13908.27) P10.13@28552.12,13949.21 v1(28552.12,13990.16) ; v1(28554.36,11316.44) P4.9@28554.36,11403.31 v1(28554.36,11490.19) P4.8@28554.36,11613.93 v1(28554.36,11700.81)
  Bottom Layer w40: P4.7@28444.13,11343.27 28492.12,11295.28 v1(28492.12,11245.57) ; P4.6@28444.13,11673.97 28488.13,11717.98 v1(28488.13,11771.67)
  Bottom Layer w50: FB11.2@28199.92,14170.57 28460.12,14170.57 MTG1.1@28462.21,14172.66
GND_OSC0: C25.2 C26.2 R110.1 U5.V11 | length 1195.5
  Top Layer w12: v1(26529,11974) 26529,11933.91 C25.2@26475.12,11880.04 26475.12,11848.16 26471.72,11844.75 26440.52,11813.53 26410.34,11813.53 26391.54,11794.73 26391.54,11678.53 26412.14,11657.93 26644.87,11657.93 26665.48,11678.53 26665.48,11790.42 26643.77,11812.13 26602.14,11812.13 26591.74,11822.53 v1(26591.74,11844.73) ; U5.V11@26569.22,12096.28 26569.22,12086.78 26585,12071 26585,11915.7 26600.12,11900.57 C26.2@26600.12,11880.04 ; v1@26591.72,11844.75 26591.72,11868.21 26600.12,11876.62 R110.1@26648.98,11876.62
  other v1: 26471.74,11844.73
GND_OSC1: C21.1 C22.1 U5.A5 | length 633.5
  Top Layer w10: U5.A5@26380.25,12631.72 26389,12640.47 26389,12666.97 v2@26380.25,12675.72
  Top Layer w20: v1(26352,12704) 26352,12739 26322,12769 C22.1@26322,12802.11 26322,12824 26310,12836 26310,12914 26326,12930 26446,12930 26458,12918 26458,12840 26447,12829 C21.1@26447,12802.11 26447,12778.45 v1(26437.12,12768.57)
  Bottom Layer w20: v1(26352,12704) v2(26378.25,12677.72)
GNDA_ADC: C31.2 C32.2 C33.2 C93.2 FB3.1 TP31.1 U5.A9 U5.E8 | length 3435.2
  Top Layer w10: C93.2@26500,13030 26484,13014 26484,12769.57 26518,12735.57 26518,12665.39 26506.23,12653.62 U5.A9@26506.23,12631.72 ; C32.2@26593.5,13067 C33.2@26639.25,13067 C31.2@26685,13067 26711.85,13067 v1(26715.24,13070.4)
  Top Layer w16: v2(26458.99,12521.48) U5.E8@26474.74,12505.73
  ART03 w10: TP31.1@25697.5,14162 25647.12,14111.62 25647.12,13780.57 25677.12,13750.57 25677.12,13331.57 25807.12,13201.57 26179.43,13201.57 26240.43,13140.57 26240.43,13034.27 26484.12,12790.57 v1(26484.12,12769.57)
  ART04 w12: v2(26458.99,12521.48) 26478.29,12502.18 26502.68,12502.18 26513.12,12512.63 26513.12,12679.51 26484.12,12708.51 v1(26484.12,12769.57)
  Bottom Layer w20: v1(26484.12,12769.57) 26460,12793.7 26460,12947.4 FB3.1@26562.6,13050 26562.6,13066.05 26626.12,13129.57 26656.06,13129.57 v1(26715.24,13070.4)
GO_H0: RA8.3 U21.31 | length 308.6
  Top Layer w6: U21.31@25582.32,11625.59 25582.32,11509.3 25669.25,11422.37 RA8.3@25669.25,11352.99
GO_H1: RA8.4 U21.30 | length 303.7
  Top Layer w6: U21.30@25562.64,11625.59 25562.64,11469.98 25637.76,11394.87 RA8.4@25637.76,11352.99
GO_H2: RA9.1 U21.29 | length 273.2
  Top Layer w6: U21.29@25542.95,11625.59 25542.95,11409.67 25544.49,11408.13 RA9.1@25544.49,11352.99
GO_H3: RA9.2 U21.28 | length 276.9
  Top Layer w6: RA9.2@25512.99,11352.99 25512.99,11403.61 25523.27,11413.89 U21.28@25523.27,11625.59
GO_H4: RA9.3 U21.27 | length 281.7
  Top Layer w6: RA9.3@25481.5,11352.99 25481.5,11410.12 25503.58,11432.2 U21.27@25503.58,11625.59
GO_H5: RA9.4 U21.26 | length 286.6
  Top Layer w6: RA9.4@25450,11352.99 25450,11417.62 25483.9,11451.52 U21.26@25483.9,11625.59
GPIO0_7: C145.1 R37.2 R50.1 R51.1 S4.2 S4.4 TP35.1 | length 1770.9
  Top Layer w6: TP35.1@26875.12,14100.57 26875.12,14055.01 26855,14034.89 R37.2@26855,14016.14 26896.14,14016.14 C145.1@26900,14020 26933.52,14020 S4.2@26968.02,14054.5 S4.4@27129.44,14054.5 ; R50.1@26937,12883 v1(26968.12,12883)
  ART03 w5.5: TP35.1@26875.12,14100.57 26862.57,14100.57 26800.12,14038.12 26800.12,13938.57 26953.12,13785.57 26953.12,12898 v1(26968.12,12883)
  Bottom Layer w6: R51.1@26937,12883 v1(26968.12,12883)
GPIO0_7SRC: R50.2 U5.C18 | length 368.1
  Top Layer w6: U5.C18@26789.7,12568.72 26790.25,12568.18 26812.73,12568.18 26823.56,12579.01 26823.56,12625.56 26856.22,12658.22 26874.74,12658.22 26883.59,12667.08 26883.59,12730.49 26937,12783.9 R50.2@26937,12850.72
GPIO0_26: U5.T11
GPIO0_27: U5.U12
GPIO1_12: U5.T12
GPIO1_13: U5.R12
GPIO1_14: U5.V13
GPIO1_15: R260.2 U5.U13 | length 2489.6
  Top Layer w6: v2(26616.47,12112.04) U5.U13@26632.22,12127.78
  ART04 w5.5: v2(26616.47,12112.04) 26560,12055.56 26560,11954.8 26618.69,11896.11 26814.49,11896.11 26854.75,11936.37 26947.56,11936.37 27006.07,11877.85 27512.37,11877.85 27524.66,11890.14 27524.66,12008.28 27731.31,12214.93 27731.31,12608.73 27784,12661.42 28063.46,12661.42 v1(28101.26,12623.62)
  Bottom Layer w6: v1(28101.26,12623.62) R260.2@28141.34,12623.62
GPIO1_16: R160.2 R253.1 | length 1800.3
  ART04 w5.5: v1(27541,12063) 27541,12064 27663,12186 27663,12629.42 27722.2,12688.62 v1(28101.34,12688.62)
  Bottom Layer w6: R160.2@26945.2,12076.61 27054.19,11967.62 27445.62,11967.62 v1(27541,12063) ; v1(28101.34,12688.62) R253.1@28141.42,12688.62
GPIO1_17: R254.2 U5.V14 | length 77.8
  Top Layer w6: v2(26647.96,12080.54) U5.V14@26663.71,12096.28
  Bottom Layer w6: v2(26647.96,12080.54) 26647.96,12048.96 R254.2@26664.92,12032
GPIO1_28: C146.1 R38.2 S5.2 S5.4 TP16.1 U5.U18 | length 724.4
  Top Layer w6: U5.U18@26789.7,12127.78 26876,12127.78 v1(26891.48,12112.3) v1@26891.48,12112.14 ; S5.2@27115.29,12099.88 27181,12099.88 v1(27200,12080.88) 27219,12099.88 S5.4@27276.71,12099.88 27339.5,12099.88 TP16.1@27378,12061.38
  Bottom Layer w6: v1(26891.48,12112.3) 26891.48,12112.14 26892.74,12110.88 C146.1@27112,12110.88 27152,12110.88 R38.2@27157,12105.88 27175,12105.88 v1(27200,12080.88)
GPIO3_18: R51.2 U5.B12 | length 549.5
  Top Layer w4.4: U5.B12@26600.72,12600.22 26616.52,12616.02 26616.52,12639
  Top Layer w6: 26616.52,12639 26616.52,12752.01 v1(26625.85,12761.34)
  Bottom Layer w6: v1(26625.85,12761.34) 26647.57,12739.62 26704.62,12739.62 26730.57,12765.57 26872,12765.57 26937,12830.57 R51.2@26937,12850.72
GPIO3_19: R259.1 U5.C13 | length 291
  Top Layer w6: v2(26616.47,12584.47) U5.C13@26632.22,12568.72
  ART03 w5.5: v2(26616.47,12584.47) 26616.47,12691.73 26666.6,12741.85 v1(26666.6,12761.34)
  Bottom Layer w6: R259.1@26626.12,12815.65 26666.6,12775.18 v1(26666.6,12761.34)
GPIO3_20: R20.2 U5.D13 | length 175.9
  Top Layer w6: U5.D13@26632.22,12537.23 v2(26647.97,12552.98)
  Bottom Layer w4.4: v2(26647.97,12552.98) 26663.96,12568.97 26761.03,12568.97 26773,12557 R20.2@26790,12557
GPIO3_21: R102.1 R167.2 TP24.1 U5.A14 | length 4944.4
  Top Layer w6: U5.A14@26663.71,12631.72 26663.71,12686.89 26721.12,12744.31 26721.12,12865.57 v1(26662.12,12924.57) 26675,12924.57 26739.12,12988.7 26739.12,13091.31 26712.92,13117.51 R167.2@26712.92,13160.61
  ART04 w5.5: TP24.1@25697.5,14062 25697.5,14020.44 25850.22,13867.72 25898.68,13867.72 25922.46,13843.94 25922.46,13584.9 25905.21,13567.65 25580.05,13567.65 25420.24,13727.46 24952.84,13727.46 v1(24744,13518.62) 24710.12,13484.75 24710.12,13398.88 24757,13352 24757,13343 24805.48,13294.52 25045.48,13294.52 25084.69,13255.31 25084.69,13187 25236.82,13034.88 26564.06,13034.88 26584.45,13014.49 26584.45,12986.25 26646.12,12924.57 v1(26662.12,12924.57)
  Bottom Layer w6: R102.1@24741.72,13553.62 24741.72,13520.91 v1(24744,13518.62)
GRN_C: R132.2 TP40.1 | length 88.9
  Top Layer w20: TP40.1@27990.56,13133.96 28003.03,13121.49 R132.2@28003.03,13050.26
GRNA: TP42.1 U14.3 | length 431.1
  Top Layer w6: U14.3@27432.66,12568 27432.66,12583.66 27468.62,12619.62 27523,12619.62 v1(27538,12604.62)
  ART03 w5.5: v1(27538,12604.62) 27574.64,12604.62 27700,12729.98 TP42.1@27700,12805
HDMI_INT: R158.2 U5.U16 | length 103.1
  Top Layer w6: U5.U16@26726.7,12127.78 v2(26742.45,12112.04)
  Bottom Layer w6: v2(26742.45,12112.04) 26747.45,12107.04 R158.2@26821.19,12107.04
HDMICLK_DISN: U5.V17 Y4.1 | length 2565.8
  Top Layer w6: U5.V17@26758.2,12096.28 v2(26773.95,12080.54) ; Y4.1@26880,13229 26930.35,13279.35 26930.35,13371.8 27048.55,13490 v1(27129.29,13490)
  ART04 w5.5: v2(26773.95,12080.54) 26799.68,12054.8 26892.86,12054.8 26915.99,12077.93 27151.48,12077.93 27423.12,12349.57 27423.12,12534.57 27465.12,12576.57 27465.12,12866.94 27414.31,12917.76 27414.31,13104.95 27393.09,13126.17 27393.09,13316.95 27220.04,13490 v1(27129.29,13490)
HSYNCH: RA1.6 U21.40 | length 220
  Top Layer w6: U21.40@25678.78,11840.16 25765.67,11840.16 25787.76,11862.25 RA1.6@25889.63,11862.25
I2C0_SCL: R3.2 U2.28 U5.C16 U7.1 | length 1492.8
  Top Layer w6: U2.28@26602.12,13510.63 26670.18,13510.63 v3(26685.12,13525.57) ; U5.C16@26726.7,12568.72 v2(26742.45,12584.47) ; v3(26926,12664.62) 26942.88,12681.5 U7.1@26978,12681.5
  ART04 w5.5: v3(26685.12,13525.57) 26724.12,13486.57 26724.12,13380.57 26824.12,13280.57 26824.12,13253.57 26931.13,13146.57 26931.13,12669.75 v3(26926,12664.62) 26945.59,12645.04 26945.59,12613.34 26932.74,12600.49 26895.65,12600.49 26873.53,12578.36 26850.24,12578.36 26823.62,12551.74 26775.17,12551.74 v2(26742.45,12584.47)
  Bottom Layer w6: v3@26685.12,13526 R3.2@26740.86,13526
I2C0_SDA: R4.2 U2.27 U5.C17 U7.3 | length 1399.6
  Top Layer w6: U2.27@26602.12,13494.88 26680.82,13494.88 v3(26684.12,13491.57) ; U5.C17@26758.2,12568.72 v2(26773.95,12584.47) ; v3(26925,12624.15) 26942.65,12606.5 U7.3@26978,12606.5
  ART04 w5.5: v3(26684.12,13491.57) 26709.12,13466.57 26709.12,13373.57 26807.12,13275.57 26807.12,13250.57 26915.83,13141.87 26915.83,12680.96 26907.25,12672.39 26907.25,12641.9 v3(26925,12624.15) 26914.85,12614 26849.21,12614 26837.22,12602 26837.22,12585.74 26818.29,12566.81 26780.29,12566.81 26773.95,12573.16 v2(26773.95,12584.47)
  Bottom Layer w6: v3(26684.12,13491.57) 26694.7,13481 R4.2@26740.86,13481
I2C1_SCL: TP20.1 U5.A16 U11.1 | length 3430.7
  Top Layer w6: U11.1@24989.8,13767.35 25022.27,13767.35 25035.38,13754.24 25035.38,13651.83 v3(25025.12,13641.57) ; U5.A16@26726.7,12631.72 26726.7,12665.5 26818.89,12757.69 26875.1,12813.9 26875.1,12963.1 TP20.1@27015.5,13103.5
  ART04 w5.5: v3(25025.12,13641.57) 25046.65,13663.09 25357.25,13663.09 25516.91,13503.44 25957.29,13503.44 26073.76,13619.9 26073.76,13703.04 26191.29,13820.57 26434.94,13820.57 26524.19,13731.33 26524.19,13660.97 26598.13,13587.03 26681.67,13587.03 26777.12,13491.57 26777.12,13409.57 26902.12,13284.57 26902.12,13216.88 TP20.1@27015.5,13103.5
I2C1_SDA: TP21.1 U5.B16 U11.2 | length 3455.6
  Top Layer w4.4: U5.B16@26726.7,12600.22 26742,12615.52 26742,12632
  Top Layer w6: U11.2@24989.8,13787.04 25029.03,13787.04 25054.12,13761.95 25054.12,13651.57 v1(25064.12,13641.57) ; 26742,12632 26742,12661.89 26887,12806.89 26887,12943.97 26951.65,13008.62 TP21.1@27015,13008.62
  ART04 w5.5: v1(25064.12,13641.57) 25355.35,13641.57 25509.31,13487.62 25967.47,13487.62 26089.91,13610.06 26089.91,13697.68 26199.81,13807.57 26405.35,13807.57 26482.24,13730.68 26482.24,13680.16 26612.5,13549.89 26699.8,13549.89 26739.12,13510.57 26739.12,13404.57 26843.12,13300.57 26843.12,13254.57 26960.81,13136.89 26960.81,13062.81 TP21.1@27015,13008.62
I2C2_SCL: R251.1 TP22.1 U5.D17 | length 2535.4
  Top Layer w4.4: U5.D17@26758.2,12537.23 26772.97,12552 26801,12552
  Top Layer w6: 26801,12552 26812.11,12552 26836.99,12576.88 26836.99,12613.98 26856.69,12633.69 v1(26872.5,12633.69) 26895,12656.18 26895,12718.03 26959.02,12782.05 26959.02,12807.94 27033,12881.91 TP22.1@27033,12887
  Bottom Layer w6: v1(26872.5,12633.69) 26902.12,12604.07 26945.61,12604.07 27022,12527.67 27022,12484.62 27048.96,12457.67 27048.96,12422.86 27071.96,12399.85 27071.96,12282.81 27123.64,12231.13 27301.96,12231.13 27317.06,12216.02 27402.71,12216.02 27452.03,12265.35 27452.03,12343.63 27465.1,12356.69 27597.14,12356.69 27623,12382.56 27623,12638.62 27719,12734.62 27925.26,12734.62 v1(28101.26,12558.62) R251.1@28141.34,12558.62
I2C2_SDA: R255.1 TP23.1 U5.D18 | length 2554.1
  Top Layer w6: U5.D18@26789.7,12537.23 26815.78,12537.23 26861.27,12582.73 v1(26861.27,12596.25) 26881.81,12596.25 26906,12620.44 26906,12702.12 26980.83,12776.95 26980.83,12809.52 27006.36,12835.05 27027.54,12835.05 27033,12829.59 TP23.1@27033,12787
  Bottom Layer w6: v1(26861.27,12596.25) 26887.26,12570.26 26887.26,12541.56 26906.86,12521.96 26932.65,12521.96 26955.35,12499.26 26955.35,12470.69 26980.96,12445.08 27009.53,12445.08 27018.63,12435.98 27018.63,12404.2 27042,12380.83 27042,12270.64 27109.37,12203.28 27280.37,12203.28 27299.06,12184.58 27411.12,12184.58 27515.04,12288.5 27579.02,12288.5 27652,12361.49 27652,12622.62 27733,12703.62 27858,12703.62 28072,12489.62 28072,12457.88 28101.26,12428.62 R255.1@28141.34,12428.62
JTAG_EMU0: R23.2 U5.C14 | length 2127.6
  Top Layer w6: U5.C14@26663.71,12568.72 v2(26679.46,12584.47) ; R23.2@27261.14,14055 v1(27261.14,14088.57)
  ART03 w5.5: v2(26679.46,12584.47) 26817.68,12722.69 26944.01,12722.69 26965.45,12701.25 27087.35,12701.25 27087.68,12701.57 27177.12,12701.57 27237.12,12761.57 27237.12,13024.62 27302.21,13089.7 27302.21,13443.2 27365,13506 27365,13984.72 v1(27261.14,14088.57)
JTAG_EMU1: R24.2 U5.B14 | length 2056.3
  Top Layer w6: U5.B14@26663.71,12600.22 26679.51,12616.02 26679.51,12681.72 26736.91,12739.12 26736.91,12766.79 v1(26755.63,12785.5) ; v1(27318.86,13979.57) R24.2@27318.86,14010
  ART03 w5.5: v1(26755.63,12785.5) 26801.56,12739.57 27193.12,12739.57 27222.12,12768.57 27222.12,12900.57 27189.12,12933.57 27189.12,13053.57 27247.12,13111.57 27247.12,13418.85 27351,13522.72 27351,13947.43 v1(27318.86,13979.57)
JTAG_TCK: U5.A12 | length 3.3
  Top Layer w6: U5.A12@26600.72,12631.72 U5.A12@26603.08,12634.08
JTAG_TDI: U5.B11
JTAG_TDO: U5.A11 | length 0.8
  Top Layer w6: U5.A11@26569.22,12631.72 U5.A11@26569.78,12632.28
JTAG_TMS: U5.C11
JTAG_TRSTN: R25.1 U5.B10 | length 1610.2
  Top Layer w6: U5.B10@26537.73,12600.22 v2(26553.48,12615.97)
  ART03 w5.5: v2(26553.48,12615.97) 26553.48,12686.48 26505.51,12734.44 26505.51,12808.18 26440.64,12873.06 26440.64,12996.23 26481.09,13036.68 26481.09,13274.97 26625,13418.87 26625,13818.83 26645.17,13839 26766.38,13839 v1(26799.53,13805.85)
  Bottom Layer w6: v1(26799.53,13805.85) 26831.54,13805.85 R25.1@26855.12,13829.43
L_BO0: C235.1 P18.21 RA10.8 | length 1148.7
  Top Layer w6: RA10.8@25356.58,11274.25 v1(25356.58,11229.12) 25356.58,11155.12 25503.08,11008.62 25883,11008.62 25967.17,11092.79 v1(25967.17,11168.68)
  Bottom Layer w6: v1(25356.58,11229.12) 25379.53,11252.07 C235.1@25379.53,11268.62 ; v1(25967.17,11168.68) 25986.86,11148.99 P18.21@25986.85,10978.27
L_BO1: C236.1 P18.22 RA10.7 | length 1086.8
  Top Layer w6: RA10.7@25325.09,11274.25 v1(25325.09,11229.12) 25325.09,11163.61 25493.08,10995.62 25890.12,10995.62 v1(26006.54,11112.04)
  Bottom Layer w6: v1(25325.09,11229.12) 25333.76,11237.8 C236.1@25333.76,11268.62 ; P18.22@26006.54,10978.27 v1(26006.54,11112.04)
L_BO2: C237.1 P18.23 RA10.6 | length 1282.6
  Top Layer w6: RA10.6@25293.59,11274.25 v1(25293.59,11229.12) 25293.59,11170.11 25483.08,10980.62 25908,10980.62 26026.23,11098.85 26026.23,11148.99 v1(26006.54,11168.68)
  Bottom Layer w6: C237.1@25288,11268.62 25288,11234.71 v1(25293.59,11229.12) ; v1(26006.54,11168.68) 26026.23,11148.99 P18.23@26026.22,10978.27
L_BO3: C238.1 P18.24 RA10.5 | length 1217
  Top Layer w6: RA10.5@25262.09,11274.25 v1(25262.09,11229.12) 25262.09,11179.6 25473.08,10968.62 25920,10968.62 26045.91,11094.53 v1(26045.91,11112.04)
  Bottom Layer w6: C238.1@25242.24,11268.62 25242.24,11248.98 v1(25262.09,11229.12) ; P18.24@26045.91,10978.27 v1(26045.91,11112.04)
L_BO4: C239.1 P18.25 RA11.8 | length 1416.1
  Top Layer w6: RA11.8@25192.24,11269.25 v1(25192.24,11224.12) 25459.74,10956.62 25931,10956.62 26065.6,11091.22 26065.6,11148.99 v1(26045.91,11168.68)
  Bottom Layer w6: v1(25192.24,11224.12) 25197.97,11229.84 C239.1@25197.97,11268.62 ; v1(26045.91,11168.68) 26065.6,11148.99 P18.25@26065.59,10978.27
